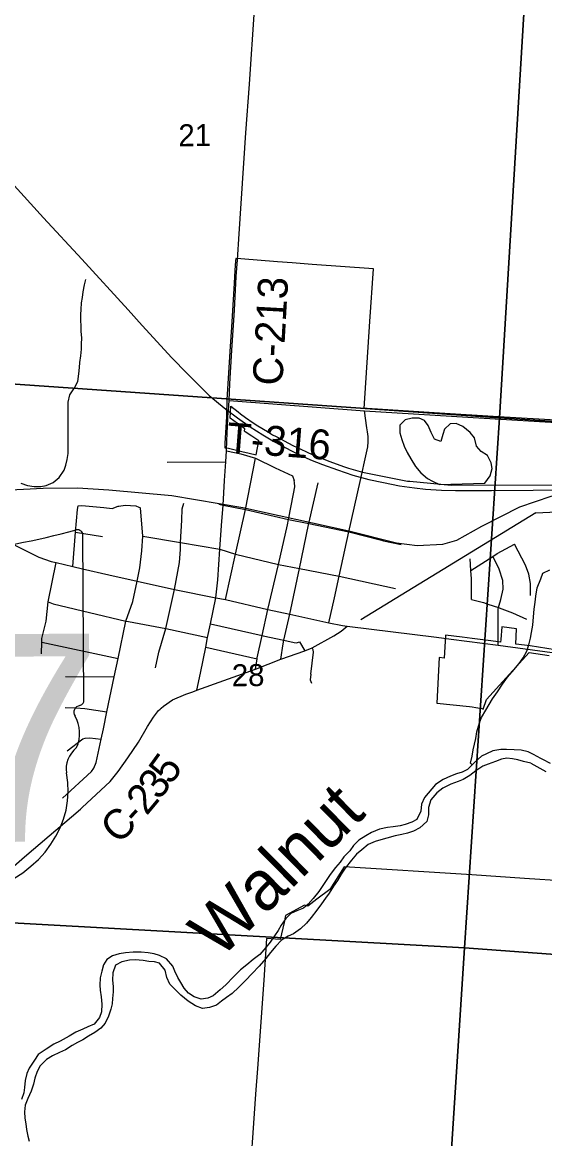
# Model space of a CAD drawing. Extents: x 114604 to 551442, y 316898 to 567001.
# Drawn here: x 236099 to 241352, y 341413 to 352635 of the extents above; entities that cross this region are included whole.
import ezdxf

# ---------------------------------------------------------------- set-up
doc = ezdxf.new("R2010")
doc.units = 0
for name, color, linetype in [('GE_P_Alignment_1000_Bearings', 7, 'Continuous'), ('GE_P_Alignment_1000_Cardinal_Points', 7, 'Continuous'), ('GE_P_Alignment_100_Cardinal_Points', 7, 'Continuous'), ('GE_P_Alignment_100_Stations', 7, 'Continuous'), ('GE_P_Alignment_500_Bearings', 7, 'Continuous'), ('GE_P_Alignment_500_Curve_Data', 7, 'Continuous'), ('MT_X_Edge_Line', 7, 'Continuous'), ('PM_P_Cells', 7, 'Continuous'), ('PM_P_CL_Double_Solid', 7, 'Continuous'), ('PM_P_Crosswalk', 7, 'Continuous'), ('PM_P_Stop_Line', 7, 'Continuous'), ('PV_X_Curb', 7, 'Continuous'), ('SN_P_Signs', 7, 'Continuous')]:
    doc.layers.add(name, color=color, linetype=linetype)

msp = doc.modelspace()

# ---------------------------------------------------------------- linework, layer by layer
at = {"layer": 'GE_P_Alignment_1000_Bearings'}
for points in [[(235623, 351423), (236313, 350671), (236696, 350255), (237162, 349745), (237303, 349588), (237603, 349263), (237755, 349104), (237978, 348883), (238145, 348748), (238262, 348660), (238389, 348570), (238517, 348488), (238618, 348428), (238710, 348378), (238846, 348309), (238998, 348238), (239119, 348189), (239269, 348135), (239422, 348084), (239585, 348040), (239730, 348008), (239892, 347976), (240042, 347956), (240155, 347942), (240316, 347933), (240454, 347930), (240819, 347929), (241236, 347931), (243391, 347940)], [(235913, 347931), (236307, 347953), (236654, 347954), (236968, 347937), (237601, 347877), (238317, 347759), (239382, 347525), (239862, 347403), (240071, 347377), (240329, 347390), (240469, 347429), (240720, 347569), (241102, 347763), (241417, 347871), (241711, 347887), (242075, 347854), (243727, 347856), (244069, 347830), (244601, 347758), (248884, 346915)]]:
    msp.add_lwpolyline(points, dxfattribs=at)
at = {"layer": 'GE_P_Alignment_1000_Cardinal_Points'}
msp.add_line((238178, 348832), (239539, 348728), dxfattribs=at)
msp.add_lwpolyline([(238999, 346084), (238993, 346024), (239008, 345991)], dxfattribs=at)
at = {"layer": 'GE_P_Alignment_100_Cardinal_Points'}
for p, q in [((237555, 348212), (238144, 348216)), ((236635, 347509), (236906, 347466)), ((239732, 347424), (239908, 347385)), ((236295, 346404), (237062, 346241)), ((237943, 346355), (238459, 346238)), ((237855, 345921), (238443, 346133)), ((236533, 346060), (237023, 346055))]:
    msp.add_line(p, q, dxfattribs=at)
for points in [[(238151, 348327), (238297, 348299), (238445, 348253), (238640, 348158), (238815, 348077), (238833, 348031)], [(238141, 346833), (238242, 347290), (238342, 347738), (238445, 348253)], [(238443, 346133), (238459, 346238), (238461, 346247), (238511, 346470), (238569, 346734), (238674, 347186), (238766, 347584), (238777, 347639), (238826, 347894), (238841, 347966), (238835, 348009), (238833, 348031)], [(238699, 346232), (238721, 346389), (238730, 346426), (238789, 346687), (238885, 347145), (238977, 347585), (238980, 347598), (239075, 348005)], [(236605, 347164), (236635, 347509), (236652, 347738), (236659, 347774)], [(236659, 347774), (236697, 347777), (236919, 347757), (237002, 347747), (237064, 347771), (237069, 347773), (237134, 347782), (237240, 347774), (237270, 347760), (237286, 347754)], [(237438, 346147), (237470, 346305), (237542, 346543), (237629, 346935), (237678, 347204), (237688, 347336), (237690, 347406), (237704, 347629), (237706, 347745), (237723, 347802)], [(238075, 347793), (238117, 347783), (238342, 347738), (238777, 347639), (238980, 347598), (239383, 347513), (239710, 347429), (239732, 347424)], [(236502, 344835), (236793, 345104), (236819, 345139), (236841, 345195), (236891, 345428), (236914, 345532), (236950, 345704), (237023, 346055), (237062, 346241), (237140, 346617), (237210, 346812), (237255, 347018), (237280, 347153), (237299, 347324), (237312, 347471), (237286, 347754)], [(237312, 347471), (237690, 347406), (238086, 347339), (238242, 347290), (238674, 347186), (238885, 347145), (239285, 347068), (239852, 346944)], [(240610, 347126), (240831, 347266), (240876, 347294), (241049, 347390)], [(241208, 346874), (241209, 346994), (241194, 347088), (241160, 347178), (241049, 347390)], [(236290, 346287), (236295, 346404), (236296, 346442), (236339, 346614), (236359, 346811), (236438, 347204)], [(240617, 346834), (240616, 347041), (240610, 347126), (240603, 347242)], [(240883, 346375), (240884, 346741), (240888, 346753), (240896, 346777), (240910, 346833), (240934, 346937), (240932, 347023), (240895, 347138), (240861, 347208), (240831, 347266)], [(236359, 346811), (236408, 346789), (237140, 346617), (237165, 346612), (237542, 346543), (237962, 346452)], [(240617, 346834), (240737, 346804), (240781, 346787), (240888, 346753), (240896, 346751), (241028, 346698), (241168, 346636)], [(237992, 346588), (238511, 346470), (238520, 346469), (238730, 346426), (238833, 346400), (238856, 346399), (238886, 346406), (238940, 346317)], [(238443, 346133), (238699, 346232), (238940, 346317), (239015, 346347), (239232, 346467), (239307, 346515), (239366, 346565)], [(238999, 346084), (239026, 346304), (239023, 346326), (239015, 346347)], [(236528, 345749), (236636, 345745), (236727, 345738), (236950, 345704)], [(236548, 345312), (236706, 345433), (236730, 345439), (236776, 345443), (236891, 345428)]]:
    msp.add_lwpolyline(points, dxfattribs=at)
at = {"layer": 'GE_P_Alignment_100_Stations'}
for points in [[(241526, 348633), (240887, 348669), (240295, 348705), (239568, 348752), (239538, 348754), (239595, 349628), (239629, 350156), (239015, 350202), (238813, 350217), (238664, 350228), (238295, 350256), (238245, 350260), (238243, 350236), (238237, 350139), (238229, 350014), (238201, 349572), (238189, 349377), (238154, 348842), (238153, 348681), (238152, 348668), (238137, 348406), (238135, 348358), (238171, 348354), (238308, 348321), (238379, 348303), (238449, 348287), (238479, 348427), (238407, 348475), (238340, 348519), (238332, 348525), (238335, 348550), (238188, 348656), (238195, 348777), (238268, 348719), (238293, 348699), (238342, 348663), (238419, 348610), (238468, 348580), (238563, 348521), (238616, 348490), (238651, 348471), (238819, 348382), (238949, 348321), (239028, 348285), (239052, 348276), (239183, 348223), (239339, 348168), (239380, 348155), (239498, 348119), (239537, 348109), (239971, 348024), (239997, 348021), (240411, 347982), (240854, 347986), (241531, 347982)], [(241543, 346314), (241207, 346366), (241061, 346383), (241069, 346538), (240994, 346547), (240920, 346557), (240911, 346431), (240909, 346405), (240862, 346411), (240783, 346422), (240705, 346432), (240624, 346441), (240522, 346454), (240356, 346473), (240353, 346415), (240342, 346243), (240290, 346250), (240266, 345790), (240595, 345757), (240623, 345755), (240659, 345748), (240721, 345736), (240734, 345730), (240768, 345829), (241197, 346300), (241398, 346270)], [(241560, 344003), (241150, 344030), (240619, 344064), (239337, 344145), (239190, 343917), (239061, 343821), (238969, 343752), (238938, 343760), (238745, 343657), (238731, 343585), (238692, 343415), (238556, 343425), (238527, 343007), (238464, 342119), (238445, 341860), (238373, 340842)]]:
    msp.add_lwpolyline(points, dxfattribs=at)
at = {"layer": 'GE_P_Alignment_500_Bearings'}
msp.add_line((238151, 348327), (238156, 348427), dxfattribs=at)
for points in [[(238262, 350248), (238279, 350509), (238347, 351523), (238382, 352014), (238433, 352765), (238451, 353102), (238468, 353345), (238483, 353652)], [(239539, 348728), (240744, 348656), (241524, 348608), (242245, 348567), (243486, 348509), (243530, 348514), (243559, 348533), (243579, 348561), (243586, 348595), (243597, 348722), (243724, 350599), (243757, 351070), (243784, 351484), (243815, 351919), (243839, 352247), (243860, 352524), (243894, 352993), (243933, 353576), (243940, 353675)], [(238171, 348729), (238178, 348832), (238187, 349001), (238206, 349339), (238231, 349743), (238251, 350081), (238262, 350248)], [(238156, 348427), (238170, 348724), (238171, 348729)], [(239496, 348018), (239559, 348309), (239572, 348369), (239577, 348418), (239576, 348470), (239571, 348517), (239565, 348559), (239539, 348728)], [(238045, 346849), (238065, 347032), (238086, 347339), (238102, 347576), (238117, 347783), (238131, 348028), (238144, 348216), (238151, 348327)], [(234213, 348255), (234900, 347929), (235244, 347773), (235527, 347623), (235763, 347511), (235944, 347419), (236265, 347260), (236390, 347214), (236438, 347204), (236605, 347164), (236705, 347141)], [(239183, 346598), (239239, 346851), (239285, 347068), (239383, 347513), (239496, 348018)], [(236705, 347141), (236970, 347080), (237255, 347018), (237629, 346935), (238045, 346849), (238141, 346833), (238569, 346734), (238789, 346687), (239183, 346598), (239320, 346573)], [(237855, 345921), (237890, 346094), (237943, 346355), (237962, 346452), (237992, 346588), (238045, 346849)], [(239320, 346573), (239366, 346565), (240265, 346454), (240411, 346436)], [(240411, 346436), (240883, 346375), (241428, 346302), (242098, 346187), (242436, 346147), (242675, 346098), (242811, 346061), (242975, 346006), (243159, 345950), (243327, 345880), (243341, 345873), (243351, 345871)], [(237484, 345730), (237495, 345740), (237518, 345760), (237609, 345823), (237744, 345882), (237812, 345905), (237855, 345921)], [(236700, 344741), (236981, 345003), (237061, 345104), (237161, 345241), (237268, 345400), (237358, 345555), (237418, 345650), (237468, 345716), (237484, 345730)], [(233206, 342376), (233285, 342364), (233497, 342330), (233586, 342320), (233634, 342317), (233699, 342313), (233787, 342329), (233887, 342357), (233964, 342392), (234050, 342441), (234354, 342696), (234737, 343025), (235428, 343644), (236122, 344247), (236685, 344727), (236700, 344741)]]:
    msp.add_lwpolyline(points, dxfattribs=at)
at = {"layer": 'GE_P_Alignment_500_Curve_Data'}
for p, q in [((236718, 345823), (236706, 347482)), ((236718, 345824), (236718, 345823))]:
    msp.add_line(p, q, dxfattribs=at)
for centre, major_axis, ratio, start_param, end_param in [((234816, 351712), (5537, 40), 0.800001, 4.814394, 5.042369), ((236648, 347488), (58.1, 0.4), 0.8, 6.141152, 7.989035), ((236706, 345701), (89.9, 0.6), 0.8, 1.883978, 3.671073), ((236656, 345816), (62.2, 0.4), 0.8, 5.05454, 6.418171), ((236135, 345488), (540, 4), 0.8, 5.934695, 6.695948), ((236932, 345131), (393, 3), 0.8, 2.387724, 3.262537), ((235175, 344907), (1385, 10), 0.8, 5.101753, 6.440018)]:
    msp.add_ellipse(centre, major_axis=major_axis, ratio=ratio, start_param=start_param, end_param=end_param, dxfattribs=at)
at = {"layer": 'MT_X_Edge_Line'}
for points in [[(240752, 348001), (240803, 348077), (240823, 348149), (240814, 348207), (240778, 348282), (240712, 348320), (240667, 348375), (240645, 348457), (240602, 348513), (240530, 348572), (240461, 348602), (240401, 348599), (240346, 348547), (240328, 348491), (240307, 348423), (240244, 348445), (240210, 348512), (240181, 348582), (240145, 348632), (240091, 348655), (240021, 348657), (239949, 348640), (239895, 348584), (239896, 348510), (239914, 348442), (239939, 348373), (239969, 348311), (240007, 348247), (240052, 348170), (240107, 348106), (240173, 348051), (240225, 348021), (240293, 347990)], [(240293, 347990), (240752, 348001)]]:
    msp.add_lwpolyline(points, dxfattribs=at)
at = {"layer": 'PM_P_Cells'}
for points in [[(236082, 348004), (236152, 347980), (236218, 347969), (236284, 347968), (236338, 347980), (236408, 348009), (236469, 348059), (236519, 348132), (236536, 348184), (236550, 348242), (236559, 348302), (236561, 348356), (236560, 348414), (236559, 348482), (236559, 348541), (236560, 348655), (236559, 348707), (236560, 348817), (236576, 348889), (236625, 348960), (236658, 349024), (236668, 349100), (236675, 349166), (236678, 349216), (236686, 349284), (236695, 349348), (236695, 349404), (236696, 349459), (236691, 349529), (236689, 349585), (236688, 349637), (236688, 349699), (236691, 349749), (236695, 349815), (236704, 349869), (236710, 349925), (236723, 349997), (236738, 350049)], [(241262, 347706), (243330, 347800)], [(241262, 347706), (239502, 346630)], [(241276, 346950), (241313, 347042), (241335, 347098), (241405, 347133)], [(240622, 345172), (240605, 345188), (240622, 345260), (240634, 345322), (240648, 345380), (240659, 345436), (240671, 345504), (240698, 345594), (240718, 345648), (240759, 345720), (240793, 345778), (240827, 345834), (240878, 345906), (240928, 345981), (240979, 346051), (241025, 346107), (241095, 346191), (241136, 346248), (241174, 346314), (241193, 346376), (241211, 346446), (241221, 346500), (241232, 346576), (241241, 346658), (241247, 346736), (241255, 346806), (241262, 346868), (241276, 346950)], [(241254, 345267), (241186, 345301), (241116, 345318), (241044, 345323), (240968, 345327), (240910, 345326), (240832, 345311), (240766, 345283), (240716, 345260), (240645, 345196), (240575, 345125), (240521, 345097), (240464, 345080), (240404, 345058), (240330, 345023), (240254, 344974), (240144, 344843), (240112, 344775), (240105, 344705), (240066, 344623), (240016, 344595), (239950, 344570), (239898, 344557), (239830, 344547), (239772, 344540), (239690, 344523), (239611, 344491), (239555, 344458), (239483, 344414), (239430, 344361), (239392, 344307), (239333, 344246), (239297, 344194), (239248, 344138), (239196, 344069), (239141, 343987), (239082, 343897), (239025, 343826), (238975, 343772), (238925, 343731), (238858, 343705), (238800, 343676), (238750, 343628), (238703, 343559), (238673, 343505), (238634, 343453), (238592, 343387), (238549, 343336), (238488, 343264), (238422, 343215), (238356, 343161), (238293, 343112), (238224, 343040), (238144, 342959), (238087, 342908), (238017, 342850), (237963, 342825), (237899, 342817), (237827, 342838), (237769, 342877), (237728, 342927), (237694, 342983), (237663, 343034), (237634, 343096), (237612, 343148), (237549, 343221), (237479, 343254), (237423, 343272), (237364, 343283), (237294, 343288), (237212, 343287), (237138, 343281), (237074, 343272), (237006, 343252), (236947, 343213), (236915, 343161), (236898, 343097), (236883, 343029), (236879, 342957), (236880, 342907), (236890, 342839), (236899, 342767), (236896, 342687), (236876, 342633), (236821, 342565), (236759, 342538), (236707, 342514), (236638, 342483), (236570, 342445), (236480, 342394), (236415, 342365), (236339, 342313), (236259, 342258), (236222, 342204), (236169, 342123), (236143, 342069), (236126, 341997), (236119, 341927), (236113, 341875), (236090, 341807)], [(241213, 345187), (241139, 345206), (241081, 345220), (241027, 345233), (240972, 345237), (240917, 345228), (240857, 345204), (240785, 345179), (240731, 345157), (240661, 345110), (240598, 345063), (240534, 345023), (240482, 345004), (240409, 344976), (240329, 344937), (240269, 344889), (240208, 344818), (240183, 344744), (240185, 344670), (240166, 344602), (240097, 344537), (240033, 344503), (239971, 344486), (239915, 344470), (239847, 344457), (239765, 344434), (239705, 344416), (239647, 344401), (239578, 344369), (239514, 344318), (239461, 344272), (239411, 344213), (239346, 344131), (239306, 344072), (239267, 344010), (239229, 343952), (239184, 343882), (239147, 343831), (239107, 343775), (239060, 343711), (239004, 343638), (238957, 343578), (238897, 343523), (238826, 343473), (238774, 343450), (238706, 343410), (238649, 343349), (238595, 343285), (238548, 343226), (238481, 343146), (238409, 343073), (238344, 343003), (238277, 342936), (238209, 342872), (238153, 342833), (238102, 342795), (238050, 342754), (237980, 342732), (237912, 342723), (237840, 342748), (237765, 342796), (237693, 342857), (237630, 342918), (237582, 342968), (237553, 343035), (237534, 343107), (237478, 343176), (237427, 343190), (237371, 343195), (237315, 343203), (237235, 343212), (237177, 343209), (237101, 343191), (237037, 343156), (237008, 343080), (237007, 343006), (237013, 342942), (237012, 342890), (237007, 342822), (237001, 342770), (236988, 342716), (236964, 342644), (236931, 342574), (236887, 342523), (236828, 342481), (236764, 342444), (236706, 342408), (236655, 342381), (236599, 342349), (236533, 342306), (236473, 342280), (236402, 342245), (236342, 342209), (236279, 342146), (236249, 342090), (236226, 342022), (236210, 341962), (236187, 341890), (236154, 341817), (236128, 341751), (236119, 341683)], [(241213, 345187), (241364, 345103)], [(241254, 345267), (241408, 345187)], [(236119, 341683), (236124, 341620), (236134, 341562), (236141, 341506), (236155, 341438), (236168, 341388)]]:
    msp.add_lwpolyline(points, dxfattribs=at)
at = {"layer": 'SN_P_Signs'}
for points in [[(235804, 354437), (241220, 354004), (240898, 348660), (235447, 349037)], [(241220, 354004), (246620, 353680), (246230, 348309), (240898, 348660)], [(240898, 348660), (240545, 343333), (235140, 343630), (235447, 349037)], [(240898, 348660), (246230, 348309), (245891, 342939), (240545, 343333)], [(235140, 343630), (240545, 343333), (240194, 337881), (235081, 338227), (234813, 338244)], [(240545, 343333), (245891, 342939), (245535, 337501), (240308, 337873), (240194, 337881)]]:
    msp.add_lwpolyline(points, close=True, dxfattribs=at)

# ---------------------------------------------------------------- texts
at = {"layer": 'GE_P_Alignment_500_Curve_Data'}
msp.add_text('317', height=2088.4, rotation=0.414, dxfattribs=at).set_placement((232266, 344370))
at = {"layer": 'PM_P_CL_Double_Solid'}
for s, rotation, p in [('C-213', 86.8389, (238713, 348978)), ('5', 54.0715, (237591, 344960)), ('3', 53.127, (237477, 344807)), ('2', 50.254, (237349, 344653)), ('C', 43.6889, (237062, 344364)), ('-', 47.4056, (237255, 344550))]:
    msp.add_text(s, height=300, rotation=rotation, dxfattribs=at).set_placement(p)
at = {"layer": 'PM_P_Crosswalk'}
msp.add_text('T-316', height=300, rotation=355.6265, dxfattribs=at).set_placement((238145, 348315))
at = {"layer": 'PM_P_Stop_Line'}
msp.add_text('Walnut', height=500, rotation=44.618, dxfattribs=at).set_placement((238085, 343209))
at = {"layer": 'PV_X_Curb'}
for s, p in [('21', (237669, 351389)), ('28', (238206, 345961))]:
    msp.add_text(s, height=221, rotation=0.4141, dxfattribs=at).set_placement(p)

doc.saveas('drawing.dxf')
